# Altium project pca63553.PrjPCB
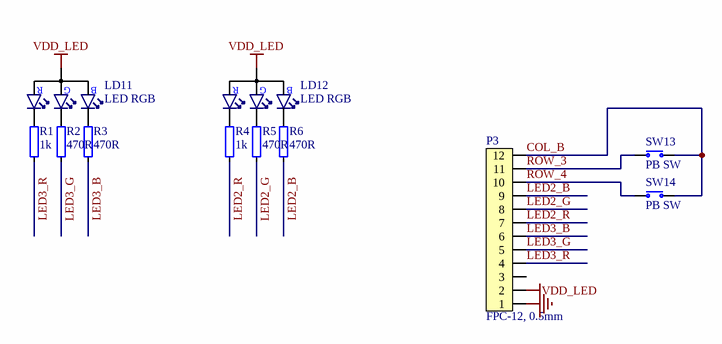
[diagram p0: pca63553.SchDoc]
SurfaceFinish: Lead-Free HASL; SoldermaskColor: Blue; SilkscreenColor: White; Revision: 0.1.0; ProjectNumber: 4456; ProjectName: nRF52 Desktop; PCBStackup: 2002; PCBRevision: 0306RUBR; PCBNumber: 400397; PCAName: PCA63553; Organization: Nordic Semiconductor; NrOfLayers: 2; BoardTitle: nRF52840 Gaming Mouse Top Buttons and LEDs Board; BoardThickness: 0.8mm; Author: RUBR
1 sheet, 11 parts. Net scope: global (net labels, ports and power ports of the same name join across sheets).
Board file: 400397.PcbDoc

## Sheet pca63553.SchDoc: =BoardTitle
size A4; Organization: Nordic Semiconductor; Revision: 0.1.0; SheetNumber: 1; SheetTotal: 1; Author: RUBR; CompanyName: Nordic Semiconductor; DrawnBy: RUBR

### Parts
LD11  LED RGB  [L3528_RGB]
LD12  LED RGB  [L3528_RGB]
P3  FPC-12, 0.5mm  [10051922-1210ELF]
R1  1k  [RESC0603X03L_C]
R2  470R  [RESC0603X03L_C]
R3  470R  [RESC0603X03L_C]
R4  1k  [RESC0603X03L_C]
R5  470R  [RESC0603X03L_C]
R6  470R  [RESC0603X03L_C]
SW13  PB SW  [Switch-PB-6.2x6.3mm-SMD]
SW14  PB SW  [Switch-PB-5.1x5.1mm-SMD]

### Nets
GND: P3.1
VDD_LED: LD11.4(A) LD12.4(A) P3.2
COL_B: P3.12 SW13.2(COM) SW14.1(N.O)
LED2_B: P3.9 R6.2
LED2_G: P3.8 R5.2
LED2_R: P3.7 R4.2
LED3_B: P3.6 R3.2
LED3_G: P3.5 R2.2
LED3_R: P3.4 R1.2
ROW_3: P3.11 SW13.1(N.O)
ROW_4: P3.10 SW14.2(COM)
NetLD11_1: LD11.1(C_RED) R1.1
NetLD11_2: LD11.2(C_GREEN) R2.1
NetLD11_3: LD11.3(C_BLUE) R3.1
NetLD12_1: LD12.1(C_RED) R4.1
NetLD12_2: LD12.2(C_GREEN) R5.1
NetLD12_3: LD12.3(C_BLUE) R6.1

Not connected (* = marked no-connect by the designer): P3 3

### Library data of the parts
LD11 LD12 = AAA3528LSEEZGKQBKS: 3.5 x 2.8 mm Surface Mount RGB LED; Manufacturer: Kingbright Company LLC; Artikkelnr Noca: N.A.
P3 = 10051922-1210ELF: 0.5mm pitch, bottom side contact, side entry SMD FPC connector; Manufacturer: FCI; Artikkelnr Noca: N.A.
R1 R4 = R0201-1k0: Resistor, ±1%, 0.05W; Note: Chip Res 1%; Artikkelnr Noca: N.A.
R2 R3 R5 R6 = R0201-470: Resistor, ±1%, 0.05W; Note: Chip Res 1%; Artikkelnr Noca: N.A.
SW13 = Switch-PB-6.2x6.3mm-SMD: Tactile Switch, SPNO, SMD, 160gf, 6.2x6.3x2.5mm; Manufacturer: Dailywell; Manufacturer Part Number: TS604VM1-025BR-R; Part number IPS: 00000007812; Artikkelnr Noca: 50019106
SW14 = Switch-PB-5.1x5.1mm-SMD: Tactile Switch, SPNO, SMD, 160gf, 5.1x5.1x1.5mm; Manufacturer: C&K Components; Manufacturer Part Number: PTS525 SM15 SMTR2 LFS; Artikkelnr Noca: N.A.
